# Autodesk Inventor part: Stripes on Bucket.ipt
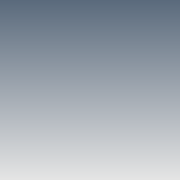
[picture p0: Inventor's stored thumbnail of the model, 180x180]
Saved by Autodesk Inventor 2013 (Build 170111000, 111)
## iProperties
Created: 2012-02
Part Number: Stripes on Bucket.ipt
Material: Aluminum-6061
Document SubType Name: Modeling
Designer: tedescj
Density: 2.71 g/cm^3
Mass: 1247.09 g
Surface Area: 3414.78 cm^2
Volume: 460.181 cm^3
Author: tedescj
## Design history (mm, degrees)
derived "Bands to bucket.ipt"
feature "Solid1::Bands to bucket.ipt"
feature "Srf7::Bands to bucket.ipt"
body "Srf1"
feature "Srf8::Bands to bucket.ipt"
body "Srf2"
feature "Srf9::Bands to bucket.ipt"
body "Srf3"
tag "TaggingFeature1"
body "Solid1"
